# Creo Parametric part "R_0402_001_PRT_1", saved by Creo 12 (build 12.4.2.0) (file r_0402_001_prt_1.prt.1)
Units: Custom; MM, KILOGRAM, SECS

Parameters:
  PTC_WM_ITERATION = "0"
  PTC_WM_VERSION = "-.0"
  PTC_WM_LIFECYCLE_STATE = "In Work"
  PTC_WM_LIFECYCLE = "MO_CADDocument"
  PTC_WM_CREATED_BY = "Maximilian Roepper (Z0017RMS: MO)"
  PTC_WM_CREATED_ON = "18-Sep-26 11:36:42 AM"
  PTC_WM_MODIFIED_BY = "Maximilian Roepper (Z0017RMS: MO)"
  PTC_WM_MODIFIED_ON = "18-Sep-26 11:36:46 AM"
  PDMLINKNUMBER = "PDM000071455046"
  PTC_WM_NAME = "r_0402_001_prt_1.prt"
  PTC_WM_NUMBER = "PDM000071455046"

Other parameters: WEIGHT, WEIGHT_FACTOR, WEIGHT_ADD, _MASS_TEMP, _DIFF_TEMP, MC_ERRORS, SUPPLIER

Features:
  1. coordinate system
  2. datum plane "PRT_YZ"
  3. datum plane "PRT_XY"
  4. datum plane "PRT_XZ"
  5. coordinate system
  6. datum axis
  7. datum axis
  8. datum axis
  9. coordinate system
  10. imported feature
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
Other named items: PRT, SIEMENS_MO, DRW_VIEW_ORG, PRT_X, PRT_Y, PRT_Z, CS0, ROUGH_GROB

Layers: 00_STD_CSYS-KSYS, 01_STD_PLANES-EBENEN, 02_STD_AXES-ACHSEN, 03_STD_CSYS-KSYS, 24_IMPORT_FEAT-IMPORT_KE

Surfaces: 18 plane, 8 cylinder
